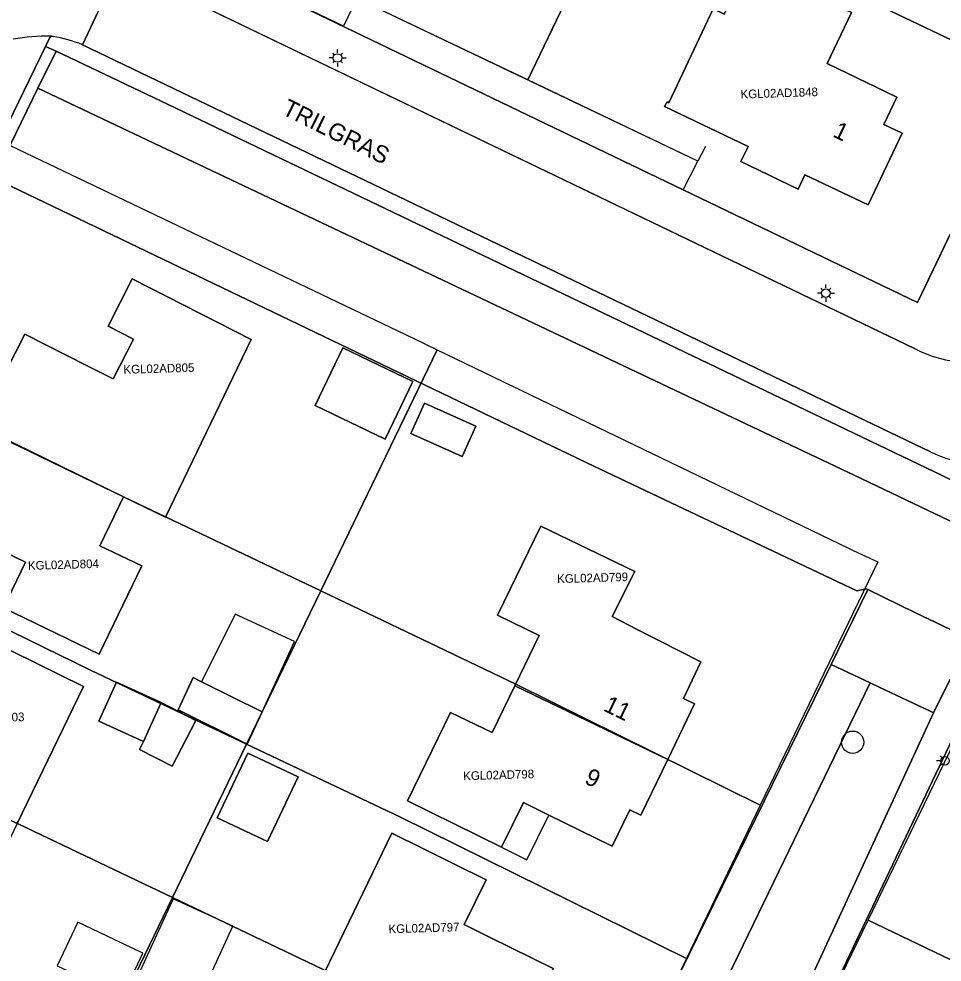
# Model space of a CAD drawing. Extents: x 124901 to 125496, y 515369 to 515789.
# Drawn here: x 125375.1 to 125428.8, y 515688.8 to 515743.6 of the extents above; entities that cross this region are included whole.
import ezdxf

# ---------------------------------------------------------------- set-up
doc = ezdxf.new("R2010")
doc.units = 0
for name, color, linetype in [('Gebouw', 7, 'Continuous'), ('Lichtmast', 7, 'Continuous'), ('Luifel', 7, 'Continuous'), ('Onbegroeid terrein', 7, 'Continuous'), ('Parkeren', 7, 'Continuous'), ('Perceelnummers', 7, 'Continuous'), ('Perceelsgrenzen', 7, 'Continuous'), ('Putten', 7, 'Continuous'), ('Scheiding', 7, 'Continuous'), ('Teksten', 7, 'Continuous'), ('Vegetatie', 7, 'Continuous'), ('Voetpad', 7, 'Continuous'), ('Water', 7, 'Continuous'), ('Wegen drempel verkeerseiland', 7, 'Continuous'), ('Wegen lokale weg', 7, 'Continuous')]:
    doc.layers.add(name, color=color, linetype=linetype)

msp = doc.modelspace()

# ---------------------------------------------------------------- linework, layer by layer
at = {"layer": 'Gebouw'}
for points in [[(125423.536, 515744.006), (125417.541, 515746.861), (125416.135, 515743.909), (125415.497, 515744.211), (125412.913, 515738.759), (125412.822, 515738.808), (125412.676, 515738.535), (125417.528, 515736.209), (125417.109, 515735.335), (125420.434, 515733.734), (125420.834, 515734.572), (125424.504, 515732.82), (125426.486, 515736.981), (125425.411, 515737.485), (125426.183, 515739.085), (125422.121, 515741.035)], [(125381.726, 515728.523), (125380.317, 515725.762), (125381.787, 515725.012), (125380.606, 515722.696), (125379.136, 515723.445), (125375.483, 515725.307), (125374.39, 515723.164), (125373.73, 515723.5), (125372.153, 515720.22), (125381.217, 515715.836), (125383.648, 515714.66), (125388.644, 515724.997)], [(125398.028, 515722.55), (125393.975, 515724.508), (125392.366, 515721.145), (125396.418, 515719.187)], [(125398.71, 515721.293), (125397.912, 515719.528), (125400.896, 515718.179), (125401.694, 515719.944)], [(125379.797, 515706.695), (125382.277, 515711.826), (125379.847, 515713), (125381.217, 515715.836), (125372.153, 515720.22), (125370.618, 515717.026), (125371.274, 515716.711), (125370.25, 515714.58), (125374.158, 515712.692), (125375.509, 515712.039), (125374.227, 515709.386)], [(125413.766, 515704.116), (125414.79, 515706.24), (125411.088, 515708.131), (125409.618, 515708.881), (125410.95, 515711.49), (125405.47, 515714.13), (125402.954, 515708.957), (125405.383, 515707.781), (125403.966, 515704.855), (125412.859, 515700.564), (125414.42, 515703.8)], [(125363.621, 515702.375), (125372.61, 515698.029), (125375.04, 515696.854), (125378.883, 515704.805), (125373.368, 515707.516), (125372.077, 515704.89), (125370.731, 515705.552), (125366.87, 515707.45), (125365.844, 515705.316), (125365.187, 515705.632)], [(125389.269, 515703.338), (125385.755, 515705.083), (125385.265, 515705.326), (125384.401, 515703.449), (125388.405, 515701.46)], [(125383.404, 515703.886), (125380.816, 515705.061), (125379.785, 515702.791), (125382.373, 515701.615)], [(125403.966, 515704.855), (125402.647, 515702.13), (125400.217, 515703.307), (125397.729, 515698.169), (125403.184, 515695.47), (125404.469, 515698.068), (125405.948, 515697.336), (125409.62, 515695.52), (125410.644, 515697.642), (125411.297, 515697.327), (125412.859, 515700.564)], [(125382.373, 515701.615), (125382.143, 515701.157), (125384.039, 515700.172), (125385.423, 515702.836), (125383.404, 515703.886)], [(125388.44, 515700.941), (125386.662, 515697.18), (125389.583, 515695.799), (125391.361, 515699.561)], [(125405.175, 515686.283), (125406.19, 515688.41), (125402.491, 515690.233), (125401.011, 515690.963), (125402.299, 515693.575), (125396.814, 515696.279), (125392.911, 515688.22), (125404.274, 515682.742), (125405.83, 515685.97)]]:
    msp.add_lwpolyline(points, close=True, dxfattribs=at)
at = {"layer": 'Lichtmast'}
for p, q in [((125393.663, 515741.66), (125393.663, 515741.86)), ((125393.363, 515741.361), (125393.163, 515741.36)), ((125393.451, 515741.572), (125393.381, 515741.643)), ((125393.875, 515741.572), (125393.946, 515741.644)), ((125393.963, 515741.36), (125394.163, 515741.36)), ((125393.451, 515741.148), (125393.379, 515741.077)), ((125393.663, 515741.06), (125393.663, 515740.86)), ((125393.875, 515741.148), (125393.945, 515741.077)), ((125422.054, 515727.985), (125422.054, 515728.185)), ((125421.754, 515727.686), (125421.554, 515727.685)), ((125421.842, 515727.897), (125421.772, 515727.968)), ((125422.266, 515727.897), (125422.337, 515727.969)), ((125422.354, 515727.685), (125422.554, 515727.685)), ((125421.842, 515727.473), (125421.77, 515727.402)), ((125422.054, 515727.385), (125422.054, 515727.185)), ((125422.266, 515727.473), (125422.336, 515727.402)), ((125428.764, 515700.701), (125428.694, 515700.772)), ((125428.676, 515700.49), (125428.476, 515700.489)), ((125428.764, 515700.277), (125428.692, 515700.206))]:
    msp.add_line(p, q, dxfattribs=at)
for centre in [(125393.663, 515741.36), (125422.054, 515727.685), (125428.976, 515700.489)]:
    msp.add_circle(centre, 0.25, dxfattribs=at)
at = {"layer": 'Luifel'}
for points in [[(125374.227, 515709.386), (125375.509, 515712.039), (125374.158, 515712.692), (125372.876, 515710.039)], [(125389.269, 515703.338), (125391.152, 515707.433), (125387.714, 515709.014), (125385.755, 515705.083)], [(125403.184, 515695.47), (125404.663, 515694.738), (125405.948, 515697.336), (125404.469, 515698.068)], [(125382.086, 515688.057), (125385.548, 515686.474), (125387.563, 515690.88), (125384.101, 515692.462)], [(125381.148, 515686.776), (125382.347, 515689.306), (125378.554, 515691.104), (125377.355, 515688.574)]]:
    msp.add_lwpolyline(points, close=True, dxfattribs=at)
at = {"layer": 'Onbegroeid terrein'}
for points in [[(125396.992, 515784.043), (125396.24, 515782.475), (125389.82, 515769.117), (125383.87, 515756.723), (125380.503, 515749.71), (125427.387, 515727.139), (125451.745, 515778.087), (125454.621, 515784.043)], [(125452.441, 515680.669), (125457.131, 515690.833), (125455.479, 515695.495), (125431.793, 515706.92), (125430.629, 515704.536), (125430.732, 515704.484), (125429.798, 515702.583), (125421.887, 515685.97)]]:
    msp.add_lwpolyline(points, dxfattribs=at)
for points in [[(125417.541, 515746.861), (125423.536, 515744.006), (125422.121, 515741.035), (125426.183, 515739.085), (125425.411, 515737.485), (125426.486, 515736.981), (125424.504, 515732.82), (125420.834, 515734.572), (125420.434, 515733.734), (125417.109, 515735.335), (125417.528, 515736.209), (125412.676, 515738.535), (125412.822, 515738.808), (125412.913, 515738.759), (125415.497, 515744.211), (125416.135, 515743.909)], [(125387.675, 515656.161), (125387.857, 515654.507), (125396.207, 515657.408), (125401.906, 515659.565), (125401.03, 515662.274), (125412.127, 515685.205), (125422.352, 515706.097), (125424.481, 515710.447), (125424.391, 515710.491), (125423.853, 515710.375), (125408.558, 515717.624), (125373.683, 515734.37), (125372.5, 515731.951), (125364.983, 515716.105), (125345.743, 515676.245), (125361.449, 515668.777), (125379.413, 515660.079)], [(125382.277, 515711.826), (125379.797, 515706.695), (125374.227, 515709.386), (125375.509, 515712.039), (125374.158, 515712.692), (125370.25, 515714.58), (125371.274, 515716.711), (125370.618, 515717.026), (125372.153, 515720.22), (125373.73, 515723.5), (125374.39, 515723.164), (125375.483, 515725.307), (125379.136, 515723.445), (125380.606, 515722.696), (125381.787, 515725.012), (125380.317, 515725.762), (125381.726, 515728.523), (125388.644, 515724.997), (125383.648, 515714.66), (125381.217, 515715.836), (125379.847, 515713)], [(125398.028, 515722.55), (125396.418, 515719.187), (125392.366, 515721.145), (125393.975, 515724.508)], [(125398.71, 515721.293), (125401.694, 515719.944), (125400.896, 515718.179), (125397.912, 515719.528)], [(125414.79, 515706.24), (125413.766, 515704.116), (125414.42, 515703.8), (125412.859, 515700.564), (125411.297, 515697.327), (125410.644, 515697.642), (125409.62, 515695.52), (125405.948, 515697.336), (125404.469, 515698.068), (125403.184, 515695.47), (125397.729, 515698.169), (125400.217, 515703.307), (125402.647, 515702.13), (125403.966, 515704.855), (125405.383, 515707.781), (125402.954, 515708.957), (125405.47, 515714.13), (125410.95, 515711.49), (125409.618, 515708.881), (125411.088, 515708.131)], [(125373.368, 515707.516), (125378.883, 515704.805), (125375.04, 515696.854), (125373.658, 515693.995), (125371.173, 515688.856), (125365.656, 515691.55), (125364.164, 515692.279), (125365.447, 515694.906), (125361.73, 515696.72), (125362.724, 515698.844), (125362.07, 515699.15), (125363.621, 515702.375), (125365.187, 515705.632), (125365.844, 515705.316), (125366.87, 515707.45), (125370.731, 515705.552), (125372.077, 515704.89)], [(125385.755, 515705.083), (125389.269, 515703.338), (125388.405, 515701.46), (125384.401, 515703.449), (125385.265, 515705.326)], [(125379.785, 515702.791), (125380.816, 515705.061), (125383.404, 515703.886), (125385.423, 515702.836), (125384.039, 515700.172), (125382.143, 515701.157), (125382.373, 515701.615)], [(125388.44, 515700.941), (125391.361, 515699.561), (125389.583, 515695.799), (125386.662, 515697.18)], [(125404.274, 515682.742), (125402.712, 515679.503), (125402.056, 515679.819), (125401.03, 515677.69), (125397.34, 515679.514), (125395.861, 515680.245), (125394.572, 515677.638), (125389.097, 515680.344), (125392.911, 515688.22), (125396.814, 515696.279), (125402.299, 515693.575), (125401.011, 515690.963), (125402.491, 515690.233), (125406.19, 515688.41), (125405.175, 515686.283), (125405.83, 515685.97)]]:
    msp.add_lwpolyline(points, close=True, dxfattribs=at)
at = {"layer": 'Parkeren'}
msp.add_lwpolyline([(125424.616, 515705.029), (125422.352, 515706.097), (125412.127, 515685.205), (125401.03, 515662.274), (125401.906, 515659.565), (125402.757, 515659.867)], close=True, dxfattribs=at)
at = {"layer": 'Perceelsgrenzen'}
for points in [[(125431.007, 515734.711), (125427.387, 515727.139), (125413.755, 515733.701), (125414.614, 515735.357), (125404.72, 515740.089), (125394.782, 515744.843), (125394.008, 515743.208), (125380.503, 515749.71), (125384.163, 515757.333), (125386.795, 515762.816), (125389.428, 515768.301), (125391.02, 515771.613), (125392.618, 515774.939), (125394.78, 515779.439), (125396.748, 515783.534), (125396.992, 515784.043)], [(125422.606, 515687.317), (125424.5, 515691.221), (125432.811, 515708.356), (125432.874, 515708.485), (125461.248, 515694.727), (125453.316, 515677.409)]]:
    msp.add_lwpolyline(points, dxfattribs=at)
for points in [[(125404.72, 515740.089), (125394.782, 515744.843), (125394.008, 515743.208), (125380.503, 515749.71), (125384.163, 515757.333), (125386.795, 515762.816), (125410.278, 515751.668), (125410.215, 515751.536)], [(125433.703, 515740.35), (125410.215, 515751.536), (125410.278, 515751.668), (125414.442, 515760.344), (125414.461, 515760.383), (125421.613, 515756.939), (125433.351, 515751.249), (125437.872, 515749.069), (125435.948, 515745.045)], [(125404.72, 515740.089), (125410.215, 515751.536), (125433.703, 515740.35), (125431.007, 515734.711), (125427.387, 515727.139), (125413.755, 515733.701), (125414.614, 515735.357)], [(125345.632, 515676.323), (125350.605, 515686.696), (125354.889, 515695.633), (125359.171, 515704.565), (125363.512, 515713.469), (125367.85, 515722.367), (125374.626, 515736.264), (125398.05, 515725.06), (125399.454, 515724.383), (125423.37, 515712.85), (125423.634, 515712.729), (125425.072, 515712.068), (125418.239, 515697.902), (125413.944, 515688.996), (125412.226, 515685.435), (125409.64, 515680.099), (125405.324, 515671.192), (125401, 515662.27), (125401.99, 515659.56), (125387.73, 515654.56), (125387.592, 515656.202), (125370.466, 515664.415)], [(125367.85, 515722.367), (125374.626, 515736.264), (125398.05, 515725.06), (125399.454, 515724.383), (125392.678, 515710.366), (125381.217, 515715.836)], [(125425.072, 515712.068), (125418.239, 515697.902), (125404.015, 515704.955), (125392.678, 515710.366), (125399.454, 515724.383), (125423.37, 515712.85), (125423.634, 515712.729)], [(125363.512, 515713.469), (125367.85, 515722.367), (125381.217, 515715.836), (125392.678, 515710.366), (125388.371, 515701.456), (125379.34, 515705.75)], [(125363.512, 515713.469), (125379.34, 515705.75), (125388.371, 515701.456), (125384.059, 515692.535), (125372.598, 515698.005), (125359.171, 515704.565)], [(125413.944, 515688.996), (125397.272, 515697.224), (125388.371, 515701.456), (125392.678, 515710.366), (125404.015, 515704.955), (125418.239, 515697.902)], [(125453.316, 515677.409), (125424.5, 515691.221), (125432.811, 515708.356), (125432.874, 515708.485), (125461.248, 515694.727)], [(125354.889, 515695.633), (125359.171, 515704.565), (125372.598, 515698.005), (125384.059, 515692.535), (125379.751, 515683.623), (125370.719, 515687.915)], [(125409.64, 515680.099), (125395.383, 515687.131), (125384.059, 515692.535), (125388.371, 515701.456), (125397.272, 515697.224), (125413.944, 515688.996), (125412.226, 515685.435)], [(125405.324, 515671.192), (125388.639, 515679.4), (125379.751, 515683.623), (125384.059, 515692.535), (125395.383, 515687.131), (125409.64, 515680.099)], [(125417.983, 515677.745), (125422.606, 515687.317), (125424.5, 515691.221), (125453.316, 515677.409), (125452.553, 515675.743), (125446.912, 515663.647)]]:
    msp.add_lwpolyline(points, close=True, dxfattribs=at)
at = {"layer": 'Putten'}
msp.add_circle((125423.61, 515701.57), 0.65, dxfattribs=at)
at = {"layer": 'Scheiding'}
msp.add_lwpolyline([(125415.054, 515736.205), (125414.614, 515735.357), (125394.782, 515744.843)], dxfattribs=at)
msp.add_lwpolyline([(125373.683, 515734.37), (125376.241, 515739.601), (125377.295, 515741.756), (125376.683, 515742.027), (125371.956, 515732.322), (125372.5, 515731.951)], close=True, dxfattribs=at)
at = {"layer": 'Vegetatie'}
for points in [[(125377.122, 515742.613), (125377.049, 515742.622), (125376.976, 515742.63), (125376.683, 515742.027), (125377.295, 515741.756), (125383.764, 515738.671), (125428.849, 515717.056), (125433.943, 515714.525), (125434.186, 515715.023), (125434.079, 515715.075), (125434.469, 515715.912), (125433.579, 515716.337), (125433.163, 515717.815)], [(125428.125, 515718.465), (125378.821, 515742.134)]]:
    msp.add_lwpolyline(points, dxfattribs=at)
msp.add_lwpolyline([(125424.616, 515705.029), (125425.14, 515704.782), (125428.111, 515703.379), (125428.315, 515703.282), (125429.265, 515705.202), (125429.368, 515705.152), (125430.529, 515707.53), (125430.152, 515707.712), (125427.225, 515709.124), (125424.481, 515710.447), (125422.352, 515706.097)], close=True, dxfattribs=at)
for centre, radius, start, end in [((125375.751, 515734.497), 8.231, 68.0998, 80.4106), ((125431.606, 515725.597), 7.937, 243.9843, 281.3124)]:
    msp.add_arc(centre, radius, start, end, dxfattribs=at)
at = {"layer": 'Voetpad'}
msp.add_line((125380.977, 515746.721), (125427.246, 515724.451), dxfattribs=at)
for points in [[(125454.621, 515784.043), (125451.745, 515778.087), (125427.387, 515727.139), (125380.503, 515749.71), (125378.719, 515750.547), (125378.28, 515749.612)], [(125344.287, 515673.229), (125345.743, 515676.245), (125364.983, 515716.105), (125372.5, 515731.951), (125371.956, 515732.322), (125376.683, 515742.027), (125376.976, 515742.63)], [(125372.6, 515642.854), (125381.355, 515645.99), (125389.202, 515648.653), (125406.911, 515654.851), (125412.818, 515667.163), (125421.887, 515685.97), (125429.798, 515702.583), (125430.732, 515704.484), (125430.629, 515704.536), (125429.368, 515705.152), (125429.265, 515705.202), (125428.315, 515703.282), (125420.361, 515686.071), (125414.125, 515673.202), (125405.801, 515656.14), (125390.738, 515650.782), (125379.528, 515646.88), (125378.796, 515648.945), (125374.603, 515647.262)]]:
    msp.add_lwpolyline(points, dxfattribs=at)
for centre, radius, start, end in [((125376.729, 515732.068), 10.565, 88.6583, 100.5292), ((125430.155, 515729.757), 6.051, 241.2669, 298.0762)]:
    msp.add_arc(centre, radius, start, end, dxfattribs=at)
at = {"layer": 'Water'}
msp.add_lwpolyline([(125456.003, 515703.306), (125447.229, 515707.992), (125435.967, 515713.52), (125435.2, 515713.901), (125433.943, 515714.525), (125428.849, 515717.056), (125383.764, 515738.671), (125377.295, 515741.756), (125376.241, 515739.601), (125423.743, 515717.088), (125433.028, 515712.65), (125434.294, 515712.044), (125450.353, 515704.367), (125456.457, 515701.452), (125459.845, 515702.706), (125460.38, 515703.822), (125460.986, 515705.088), (125462.592, 515708.439), (125461.108, 515708.964), (125459.704, 515705.7)], dxfattribs=at)
msp.add_lwpolyline([(125434.294, 515712.044), (125433.028, 515712.65), (125423.743, 515717.088), (125376.241, 515739.601), (125373.683, 515734.37), (125408.558, 515717.624), (125423.853, 515710.375), (125424.391, 515710.491), (125424.481, 515710.447), (125427.225, 515709.124), (125430.152, 515707.712), (125430.529, 515707.53), (125431.793, 515706.92), (125455.479, 515695.495), (125457.131, 515690.833), (125459.845, 515702.706), (125456.457, 515701.452), (125450.353, 515704.367)], close=True, dxfattribs=at)
at = {"layer": 'Wegen drempel verkeerseiland'}
for points in [[(125378.821, 515742.134), (125380.977, 515746.721)], [(125376.976, 515742.63), (125377.049, 515742.622), (125377.122, 515742.613)]]:
    msp.add_lwpolyline(points, dxfattribs=at)
for centre, radius, start, end in [((125376.729, 515732.068), 10.565, 88.6583, 100.5292), ((125375.751, 515734.497), 8.231, 68.0998, 80.4106)]:
    msp.add_arc(centre, radius, start, end, dxfattribs=at)
at = {"layer": 'Wegen lokale weg'}
for points in [[(125427.246, 515724.451), (125380.977, 515746.721), (125378.821, 515742.134), (125428.125, 515718.465)], [(125425.14, 515704.782), (125424.616, 515705.029), (125402.757, 515659.867), (125401.906, 515659.565), (125396.207, 515657.408), (125387.857, 515654.507), (125385.018, 515653.521), (125361.779, 515664.844), (125345.959, 515672.271), (125344.963, 515672.755), (125344.617, 515672.981), (125344.287, 515673.229)], [(125370.197, 515655.148), (125377.898, 515651.479), (125378.796, 515648.945), (125379.528, 515646.88), (125390.738, 515650.782), (125405.801, 515656.14), (125414.125, 515673.202), (125420.361, 515686.071), (125428.315, 515703.282), (125428.111, 515703.379), (125425.14, 515704.782)]]:
    msp.add_lwpolyline(points, dxfattribs=at)
for centre, radius, start, end in [((125430.155, 515729.757), 6.051, 241.2669, 298.0762), ((125431.606, 515725.597), 7.937, 243.9843, 281.3124)]:
    msp.add_arc(centre, radius, start, end, dxfattribs=at)

# ---------------------------------------------------------------- texts
at = {"layer": 'Perceelnummers'}
for s, rotation, p in [('KGL02AD1848', 1.8329, (125417.098, 515739.002)), ('KGL02AD805', 1.6343, (125381.216, 515722.996)), ('KGL02AD804', 1.6343, (125375.664, 515711.593)), ('KGL02AD799', 1.6346, (125406.431, 515710.824)), ('KGL02AD803', 1.6342, (125371.336, 515702.683)), ('KGL02AD798', 1.6346, (125400.969, 515699.362)), ('KGL02AD797', 1.6345, (125396.629, 515690.459))]:
    msp.add_text(s, height=0.5, rotation=rotation, dxfattribs=at).set_placement(p)
at = {"layer": 'Teksten'}
for s, rotation, p in [('TRILGRAS', 333.6, (125390.361, 515738.121)), ('1', 334.5, (125422.395, 515736.812)), ('11', 334.2, (125409.061, 515703.426)), ('9', 334.2, (125407.958, 515699.208))]:
    msp.add_text(s, height=1, rotation=rotation, dxfattribs=at).set_placement(p)

doc.saveas('drawing.dxf')
